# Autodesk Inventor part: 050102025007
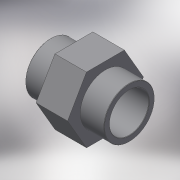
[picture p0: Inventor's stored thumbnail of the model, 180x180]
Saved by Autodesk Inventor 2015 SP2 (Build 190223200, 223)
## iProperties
Created: 2017-10
Part Number: 050102025007
Material: Generic
Description: PLASSON SOCKET ADAPTOR THR-CEM 25-3/4"
Document SubType Name: Modeling
Designer: KIM
Density: 1 g/cm^3
Appearance: Default
Author: KIM
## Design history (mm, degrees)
derived "050102.ipt"
feature "Solid1::050102.ipt"
tag "TaggingFeature1"
body "Solid1"
other parameters: "d1" = 25, "d3" = 24.117, "d4" = 22.5, "d5" = 19, "d6" = 18, "d8" = 28.75, "d10" = 12.6, "d13" = 0, "d14" = 0.25, "d15" = 12, "d_" = 25, "G_" = 24.117, "B_" = 12, "l_" = 19, "lt_" = 18
